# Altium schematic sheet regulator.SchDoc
size A4
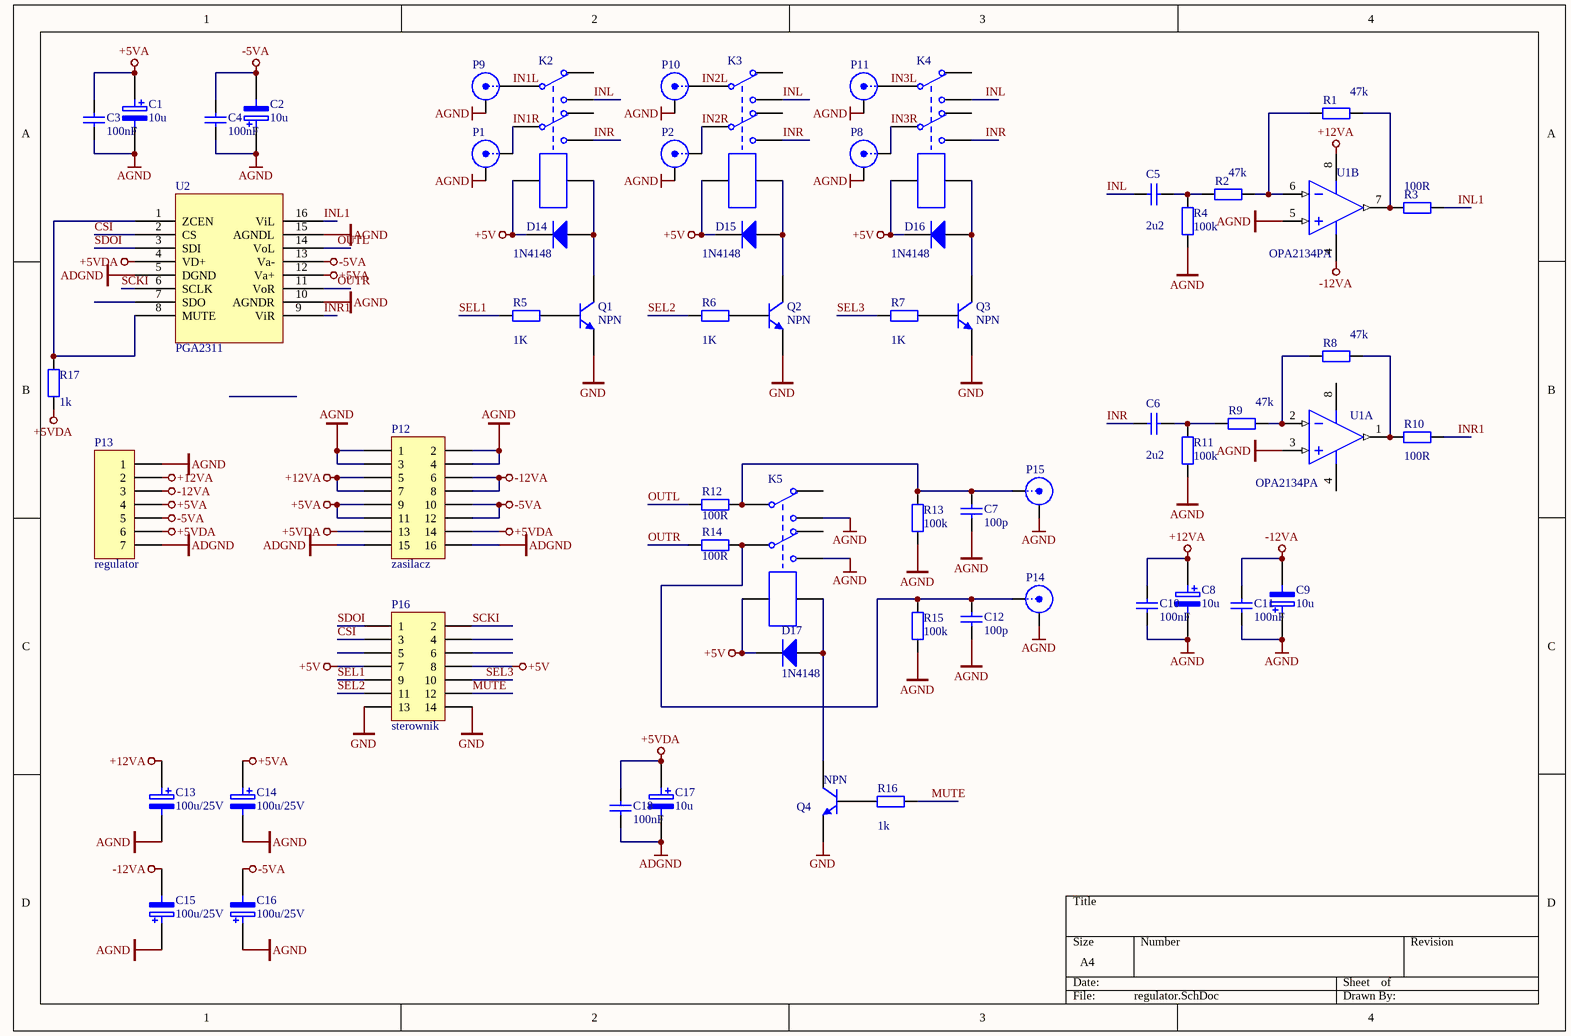
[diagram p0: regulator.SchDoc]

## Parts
C1  value 10u  [3.5X2.8X1.9]
C2  value 10u  [3.5X2.8X1.9]
C3  value 100nF  [C1206]  (hidden comment: Cap)
C4  value 100nF  [C1206]  (hidden comment: Cap)
C5  value 2u2  [RAD0.2]  (hidden comment: Cap)
C6  value 2u2  [RAD0.2]  (hidden comment: Cap)
C7  value 100p  [RAD-0.1]  (hidden comment: Cap)
C8  value 10u  [3.5X2.8X1.9]
C9  value 10u  [3.5X2.8X1.9]
C10  value 100nF  [C1206]  (hidden comment: Cap)
C11  value 100nF  [C1206]  (hidden comment: Cap)
C12  value 100p  [RAD-0.1]  (hidden comment: Cap)
C13  value 100u/25V  [RB.2/.3]
C14  value 100u/25V  [RB.2/.3]
C15  value 100u/25V  [RB.2/.3]
C16  value 100u/25V  [RB.2/.3]
C17  value 10u  [3.5X2.8X1.9]
C18  value 100nF  [C1206]  (hidden comment: Cap)
D14  1N4148  [DO-35]
D15  1N4148  [DO-35]
D16  1N4148  [DO-35]
D17  1N4148  [DO-35]
K2  Relay-DPDT  [Axicom_rel]  (value not drawn)
K3  Relay-DPDT  [Axicom_rel]  (value not drawn)
K4  Relay-DPDT  [Axicom_rel]  (value not drawn)
K5  Relay-DPDT  [Axicom_rel]  (value not drawn)
P1  BNC  [RCA_P]  (value not drawn)
P2  BNC  [RCA_P]  (value not drawn)
P8  BNC  [RCA_P]  (value not drawn)
P9  BNC  [RCA_P]  (value not drawn)
P10  BNC  [RCA_P]  (value not drawn)
P11  BNC  [RCA_P]  (value not drawn)
P12  zasilacz  [HDR2X8]
P13  regulator  [HDR1X7]
P14  BNC  [RCA_P]  (value not drawn)
P15  BNC  [RCA_P]  (value not drawn)
P16  sterownik  [HDR2X7]
Q1  NPN  [TO-226-AA]
Q2  NPN  [TO-226-AA]
Q3  NPN  [TO-226-AA]
Q4  NPN  [TO-226-AA]
R1  value 47k  [C1206]  (hidden comment: Res2)
R2  value 47k  [C1206]  (hidden comment: Res2)
R3  value 100R  [C1206]  (hidden comment: Res2)
R4  value 100k  [C1206]  (hidden comment: Res2)
R5  value 1K  [C1206]  (hidden comment: Res2)
R6  value 1K  [C1206]  (hidden comment: Res2)
R7  value 1K  [C1206]  (hidden comment: Res2)
R8  value 47k  [C1206]  (hidden comment: Res2)
R9  value 47k  [C1206]  (hidden comment: Res2)
R10  value 100R  [C1206]  (hidden comment: Res2)
R11  value 100k  [C1206]  (hidden comment: Res2)
R12  value 100R  [C1206]  (hidden comment: Res2)
R13  value 100k  [C1206]  (hidden comment: Res2)
R14  value 100R  [C1206]  (hidden comment: Res2)
R15  value 100k  [C1206]  (hidden comment: Res2)
R16  value 1k  [1206]
R17  value 1k  [1206]
U1  OPA2134PA  [TI-P8]  (parts A,B of 2)
U2  PGA2311  [DIP16]

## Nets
+5V: D14.2(K) D15.2(K) D16.2(K) D17.2(K) K2.7 K3.7 K4.7 K5.7 P16.7 P16.8
+5VA: C1.1 C3.1 C14.1 P12.9 P12.11 P13.4 U2.12(Va+)
+5VDA: C17.1 C18.1 P12.13 P12.14 P13.6 R17.2 U2.4(VD+)
+12VA: C8.1 C10.1 C13.1 P12.5 P12.7 P13.2 U1.8(V+)
-5VA: C2.2 C4.1 C16.2 P12.10 P12.12 P13.5 U2.13(Va-)
-12VA: C9.2 C11.1 C15.2 P12.6 P12.8 P13.3 U1.4(V-)
ADGND: C17.2 C18.2 P12.15 P12.16 P13.7 U2.5(DGND)
AGND: C1.2 C2.1 C3.2 C4.2 C7.1 C8.2 C9.1 C10.2 C11.2 C12.1 C13.2 C14.2 C15.1 C16.1 K5.3 K5.6 P1.2(Y) P2.2(Y) P8.2(Y) P9.2(Y) P10.2(Y) P11.2(Y) P12.1 P12.2 P12.3 P12.4 P13.1 P14.2(Y) P15.2(Y) R4.1 R11.1 R13.1 R15.1 U1.3(IN_A+) U1.5(IN_B+) U2.10(AGNDR) U2.15(AGNDL)
GND: P16.13 P16.14 Q1.3(E) Q2.3(E) Q3.3(E) Q4.3(E)
CSI: P16.3 U2.2(CS)
IN1L: K2.1 P9.1(X)
IN1R: K2.4 P1.1(X)
IN2L: K3.1 P10.1(X)
IN2R: K3.4 P2.1(X)
IN3L: K4.1 P11.1(X)
IN3R: K4.4 P8.1(X)
INL: C5.1 K2.3 K3.3 K4.3
INL1: R3.2 U2.16(ViL)
INR: C6.1 K2.6 K3.6 K4.6
INR1: R10.2 U2.9(ViR)
MUTE: P16.12 R16.1
OUTL: R12.2 U2.14(VoL)
OUTR: R14.2 U2.11(VoR)
SCKI: P16.2 U2.6(SCLK)
SDOI: P16.1 U2.3(SDI)
SEL1: P16.9 R5.1
SEL2: P16.11 R6.1
SEL3: P16.10 R7.1
NetC5_2: C5.2 R2.1 R4.2
NetC6_2: C6.2 R9.1 R11.2
NetC7_2: C7.2 K5.1 P15.1(X) R12.1 R13.2
NetC12_2: C12.2 K5.4 P14.1(X) R14.1 R15.2
NetD14_1: D14.1(A) K2.8 Q1.1(C)
NetD15_1: D15.1(A) K3.8 Q2.1(C)
NetD16_1: D16.1(A) K4.8 Q3.1(C)
NetD17_1: D17.1(A) K5.8 Q4.1(C)
NetQ1_2: Q1.2(B) R5.2
NetQ2_2: Q2.2(B) R6.2
NetQ3_2: Q3.2(B) R7.2
NetQ4_2: Q4.2(B) R16.2
NetR1_1: R1.1 R2.2 U1.6(IN_B-)
NetR1_2: R1.2 R3.1 U1.7(OUT_B)
NetR8_1: R8.1 R9.2 U1.2(IN_A-)
NetR8_2: R8.2 R10.1 U1.1(OUT_A)
NetR17_1: R17.1 U2.1(ZCEN) U2.8(MUTE)

Not connected (* = marked no-connect by the designer): K2 2 5; K3 2 5; K4 2 5; K5 2 5; P16 4 5 6; U2 7(SDO)

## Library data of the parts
C1 C2 C8 C9 C13-C17 = ELECTRO2: Electrolytic Capacitor
C3-C7 C10-C12 C18 = Cap: Capacitor
D14-D17 = Diode 1N4148: High Conductance Fast Diode
K2-K5 = Relay-DPDT: Dual-Pole Dual-Throw Relay
P1 P2 P8-P11 P14 P15 = BNC: BNC Elbow Connector
P12 = Header 8X2: Header, 8-Pin, Dual row
P13 = MHDR1X7: Header, 7-Pin
P16 = Header 7X2: Header, 7-Pin, Dual row
Q1-Q4 = NPN: NPN Bipolar Transistor
R1-R17 = Res2: Resistor
U1 = OPA2134PA: SoundPlus(TM) High Performance Audio Operational Amplifier, 5 to 36 V, -40 to 125 degC, 8-pin DIP (P8), Green (RoHS & no Sb/Br); Manufacturer: Texas Instruments; GBW(Typ)(MHz): 8; Iq per channel(Max)(mA): 5; Number of Channels: 2; Vmax(V): 36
